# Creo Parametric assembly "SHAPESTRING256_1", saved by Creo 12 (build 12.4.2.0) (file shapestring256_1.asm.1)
Units: Custom; MM, KILOGRAM, SECS

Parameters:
  PTC_WM_ITERATION = "0"
  PTC_WM_VERSION = "-.0"
  PTC_WM_LIFECYCLE_STATE = "In Work"
  PTC_WM_LIFECYCLE = "MO_CADDocument"
  PTC_WM_CREATED_BY = "Maximilian Roepper (Z0017RMS: MO)"
  PTC_WM_CREATED_ON = "18-Sep-26 11:36:42 AM"
  PTC_WM_MODIFIED_BY = "Maximilian Roepper (Z0017RMS: MO)"
  PTC_WM_MODIFIED_ON = "18-Sep-26 11:36:46 AM"
  PDMLINKNUMBER = "PDM000071455195"
  PTC_WM_NUMBER = "PDM000071455195"

Other parameters: WEIGHT, WEIGHT_FACTOR, WEIGHT_ADD, MC_ERRORS, SUPPLIER

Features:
  1. coordinate system
  2. imported feature
  3. component "SHAPESTRING001_1"
  4. component "SHAPESTRING254_1"
  5. component "SHAPESTRING255_1"

Other named items: DRW_VIEW_ORG, ROUGH-GROB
